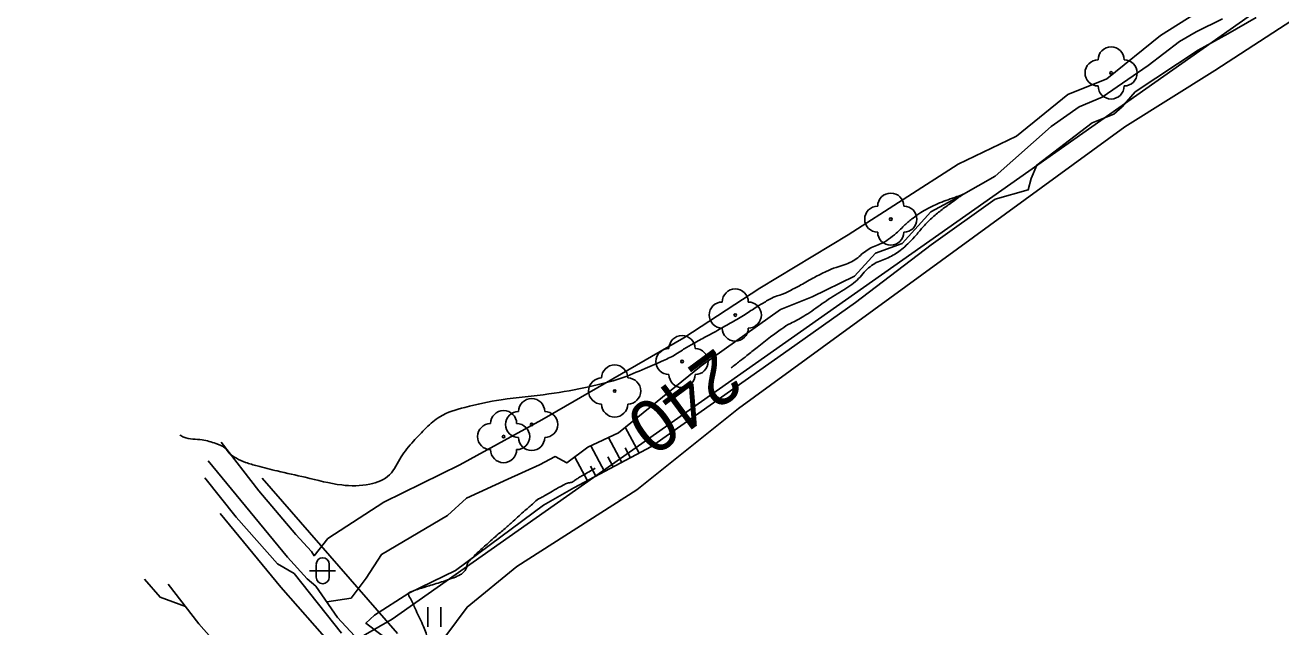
# Model space of a CAD drawing. Extents: x -478000 to -474772, y -1116847 to -1114124.
# Drawn here: x -477061.8 to -476965.5, y -1115018.8 to -1114972.6 of the extents above; entities that cross this region are included whole.
import ezdxf

# ---------------------------------------------------------------- set-up
doc = ezdxf.new("R2010")
doc.units = 0
for name, color, linetype in [('NadzemniVedeniSdelovaci', 7, 'Continuous'), ('ObPÚ', 7, 'Continuous'), ('OstatniRozhrani', 7, 'Continuous'), ('PopisneZnackyKultura', 7, 'Continuous'), ('RozhraniKultur', 7, 'Continuous'), ('RozhraniVozovky', 7, 'Continuous'), ('Teren_HranaSvahu', 7, 'Continuous'), ('Teren_PataSvahu', 7, 'Continuous'), ('Vrstevnice_hlavni', 7, 'Continuous'), ('Vrstevnice_popis', 7, 'Continuous'), ('VyskoveSrafy', 7, 'Continuous'), ('ZnackyStromu', 7, 'Continuous')]:
    doc.layers.add(name, color=color, linetype=linetype)

msp = doc.modelspace()

# ---------------------------------------------------------------- linework, layer by layer
at = {"layer": 'NadzemniVedeniSdelovaci'}
msp.add_line((-477043.667, -1115007.336), (-477033.291, -1115019.258), dxfattribs=at)
at = {"layer": 'ObPÚ'}
msp.add_lwpolyline([(-477231.42, -1115250.62), (-477154.22, -1115173.58), (-477134.18, -1115148.75), (-477133.16, -1115130.26), (-477132.09, -1115111.94), (-477138.91, -1115081.32), (-477119.74, -1115082.72), (-477097.23, -1115062.71), (-477080.55, -1115086.81), (-477072.47, -1115083.76), (-477045.85, -1115063.61), (-477043.93, -1115064.09), (-477025.31, -1115049.55), (-477043.48, -1115030.71), (-477047.46, -1115026.08), (-477033.7, -1115018.17), (-476933.96, -1114947.92), (-476834.35, -1114877.76), (-476714.64, -1114803.8), (-476602.93, -1114745.91), (-476491.34, -1114705.52), (-476390.17, -1114678.77), (-476300.68, -1114655.71)], dxfattribs=at)
at = {"layer": 'OstatniRozhrani'}
msp.add_lwpolyline([(-477052.686, -1115015.087), (-477051.49, -1115016.468), (-477049.548, -1115017.189)], dxfattribs=at)
at = {"layer": 'PopisneZnackyKultura'}
for p, q in [((-477039.525, -1115013.954), (-477039.525, -1115014.954)), ((-477038.525, -1115013.954), (-477038.525, -1115014.954)), ((-477040.025, -1115014.454), (-477038.025, -1115014.454)), ((-477030.962, -1115018.748), (-477030.962, -1115017.248)), ((-477029.962, -1115018.748), (-477029.962, -1115017.248))]:
    msp.add_line(p, q, dxfattribs=at)
for centre, start, end in [((-477039.017, -1115013.947), 0, 180), ((-477039.017, -1115014.947), 180, 0)]:
    msp.add_arc(centre, 0.5, start, end, dxfattribs=at)
at = {"layer": 'RozhraniKultur'}
for points in [[(-476813.378, -1114867.607), (-476821.938, -1114874.168), (-476829.956, -1114879.12), (-476839.311, -1114884.67), (-476847.948, -1114890.456), (-476853.558, -1114895.098), (-476860.628, -1114902.12), (-476864.524, -1114905.371), (-476870.261, -1114908.32), (-476877.101, -1114911.945), (-476885.307, -1114917.277), (-476891.328, -1114922.421), (-476896.91, -1114927.094), (-476901.992, -1114930.406), (-476908.574, -1114933.159), (-476916.772, -1114938.373), (-476929.13, -1114946.86), (-476942.484, -1114956.21), (-476956.292, -1114966.757), (-476970.592, -1114976.052), (-476977.493, -1114980.375)], [(-476977.493, -1114980.375), (-477007.129, -1115002.001), (-477014.915, -1115008.242), (-477024.119, -1115014.107), (-477027.941, -1115017.232), (-477029.578, -1115019.427), (-477026.9, -1115024.33), (-477020.646, -1115031.926), (-477009.657, -1115041.804), (-476989.625, -1115058.533), (-476972.959, -1115072.298), (-476959.884, -1115083.606), (-476949.57, -1115092.134), (-476936.86, -1115101.458), (-476916.801, -1115117.809), (-476898.41, -1115131.913), (-476893.29, -1115135.894), (-476884.407, -1115144.075), (-476873.818, -1115152.879), (-476869.38, -1115155.33)]]:
    msp.add_lwpolyline(points, dxfattribs=at)
at = {"layer": 'RozhraniVozovky'}
msp.add_line((-477050.872, -1115015.476), (-477048.51, -1115018.53), dxfattribs=at)
for points in [[(-476865.295, -1115165.15), (-476877.91, -1115155.046), (-476889.001, -1115146.126), (-476898.45, -1115138.608), (-476912.991, -1115126.893), (-476925.609, -1115116.576), (-476934.243, -1115109.589), (-476945.7, -1115100.408), (-476959.339, -1115089.601), (-476971.594, -1115079.598), (-476985.634, -1115068.114), (-477000.032, -1115056.392), (-477012.922, -1115045.335), (-477014.574, -1115043.636), (-477017.158, -1115041.291), (-477019.005, -1115039.725), (-477027.483, -1115031.623), (-477037.022, -1115021.628), (-477042.231, -1115015.698), (-477046.885, -1115010.045)], [(-477039.9, -1115028.25), (-477040.95, -1115027.09), (-477048.51, -1115018.53)]]:
    msp.add_lwpolyline(points, dxfattribs=at)
at = {"layer": 'Teren_HranaSvahu'}
for points in [[(-477046.814, -1115004.569), (-477043.911, -1115008.321), (-477041.082, -1115011.657), (-477039.877, -1115012.958), (-477039.679, -1115013.294), (-477038.62, -1115011.959), (-477034.327, -1115009.177), (-477028.512, -1115006.311), (-477022.216, -1115002.869), (-477011.316, -1114996.56), (-477005.49, -1114992.751), (-476998.708, -1114988.675), (-476990.274, -1114983.233), (-476985.811, -1114981.102), (-476981.858, -1114977.885), (-476978.88, -1114976.69), (-476974.77, -1114973.364), (-476968.548, -1114969.434)], [(-476967.424, -1114971.995), (-476969.6, -1114973.246), (-476971.86, -1114974.504), (-476976.701, -1114977.7), (-476977.711, -1114978.842), (-476978.346, -1114979.394), (-476979.993, -1114980.08), (-476984.258, -1114983.31), (-476984.676, -1114984.35), (-476984.921, -1114985.216), (-476987.44, -1114985.918), (-476992.351, -1114989.432), (-476998.162, -1114993.869), (-477003.252, -1114997.472), (-477013.794, -1115004.916), (-477019.756, -1115008.089), (-477022.074, -1115009.414), (-477025.351, -1115011.83), (-477028.825, -1115014.429), (-477032.418, -1115016.155), (-477035.055, -1115017.858), (-477035.707, -1115018.475), (-477032.661, -1115020.769)], [(-477037.585, -1115019.228), (-477041.218, -1115014.655), (-477042.497, -1115013.904), (-477045.656, -1115010.33), (-477048.061, -1115007.323)]]:
    msp.add_lwpolyline(points, dxfattribs=at)
at = {"layer": 'Teren_PataSvahu'}
for points in [[(-476969.998, -1114972.089), (-476972.036, -1114973.082), (-476973.311, -1114973.829), (-476975.701, -1114975.674), (-476979.23, -1114978.108), (-476981, -1114978.845), (-476983.152, -1114980.36), (-476987.439, -1114984.163), (-476990.054, -1114985.64), (-476992.38, -1114986.911), (-476994.571, -1114989.337), (-476996.61, -1114990.084), (-476998.235, -1114991.827), (-477001.467, -1114993.417), (-477003.916, -1114994.393), (-477009.987, -1114998.722), (-477016.342, -1115003.86), (-477018.68, -1115004.963), (-477020.285, -1115006.165), (-477021.194, -1115005.678), (-477022.397, -1115006.322), (-477024.812, -1115007.414), (-477027.993, -1115008.882), (-477029.446, -1115010.207), (-477034.517, -1115013.197), (-477035.689, -1115015.026), (-477036.844, -1115016.545), (-477038.709, -1115016.831)], [(-477047.805, -1115006.016), (-477041.728, -1115013.393), (-477040.206, -1115015.068), (-477039.547, -1115015.621), (-477037.87, -1115018.041), (-477036.57, -1115019.43), (-477033.66, -1115022.664), (-477026.482, -1115030.497), (-477018.989, -1115037.803), (-477016.248, -1115040.091)]]:
    msp.add_lwpolyline(points, dxfattribs=at)
at = {"layer": 'Vrstevnice_hlavni'}
for points in [[(-477049.979, -1115004.029), (-477049.673, -1115004.193), (-477048.26, -1115004.404), (-477047.204, -1115004.683), (-477046.505, -1115005.027), (-477046.164, -1115005.438), (-477045.639, -1115005.805), (-477044.929, -1115006.127), (-477044.034, -1115006.405), (-477042.508, -1115006.787), (-477040.351, -1115007.273), (-477037.562, -1115007.863), (-477035.407, -1115007.799), (-477033.886, -1115007.079), (-477033, -1115005.704), (-477032.062, -1115004.503), (-477031.073, -1115003.477), (-477030.034, -1115002.625), (-477028.119, -1115001.907), (-477025.328, -1115001.324), (-477021.663, -1115000.876), (-477018.599, -1115000.325), (-477016.138, -1114999.672), (-477014.278, -1114998.917), (-477012.873, -1114998.304), (-477011.923, -1114997.835), (-477011.428, -1114997.509), (-477010.705, -1114997.08), (-477009.754, -1114996.549), (-477008.574, -1114995.914), (-477007.491, -1114995.299), (-477006.505, -1114994.702), (-477005.616, -1114994.125), (-477004.874, -1114993.69), (-477004.28, -1114993.398), (-477003.833, -1114993.249), (-477003.188, -1114992.955), (-477002.345, -1114992.516), (-477001.305, -1114991.933), (-477000.403, -1114991.481), (-476999.64, -1114991.162), (-476999.016, -1114990.973), (-476998.464, -1114990.728), (-476997.985, -1114990.425), (-476997.579, -1114990.066), (-476997.143, -1114989.765), (-476996.676, -1114989.524), (-476996.178, -1114989.342), (-476995.627, -1114989.011), (-476995.023, -1114988.533), (-476994.365, -1114987.907), (-476993.741, -1114987.384), (-476993.153, -1114986.963), (-476992.599, -1114986.645), (-476992.009, -1114986.355), (-476991.383, -1114986.092), (-476990.719, -1114985.856), (-476990.255, -1114985.689), (-476989.991, -1114985.591), (-476989.925, -1114985.561), (-476989.901, -1114985.553), (-476989.919, -1114985.568), (-476989.977, -1114985.605), (-476990.02, -1114985.633), (-476990.048, -1114985.653), (-476990.061, -1114985.663), (-476990.326, -1114985.857), (-476990.841, -1114986.233), (-476991.608, -1114986.792), (-476992.308, -1114987.388), (-476992.94, -1114988.02), (-476993.504, -1114988.689), (-476994.025, -1114989.245), (-476994.503, -1114989.688), (-476994.937, -1114990.017), (-476995.402, -1114990.301), (-476995.899, -1114990.54), (-476996.428, -1114990.734), (-476996.92, -1114991.026), (-476997.375, -1114991.417), (-476997.795, -1114991.906), (-476998.298, -1114992.365), (-476998.884, -1114992.793), (-476999.553, -1114993.19), (-477000.214, -1114993.61), (-477000.867, -1114994.052), (-477001.512, -1114994.518), (-477002.106, -1114994.907), (-477002.649, -1114995.22), (-477003.142, -1114995.458), (-477003.814, -1114995.885), (-477004.665, -1114996.502)], [(-477004.665, -1114996.502), (-477005.695, -1114997.309), (-477006.489, -1114997.933), (-477007.047, -1114998.372), (-477007.691, -1114998.882)], [(-477017.894, -1115036.673), (-477018.831, -1115035.848), (-477019.673, -1115035.079), (-477020.422, -1115034.367), (-477021.076, -1115033.712), (-477022.168, -1115032.564), (-477023.697, -1115030.923), (-477025.662, -1115028.788), (-477027.122, -1115027.188), (-477028.074, -1115026.123), (-477028.52, -1115025.593), (-477029.034, -1115024.943), (-477029.617, -1115024.173), (-477030.269, -1115023.282), (-477030.708, -1115022.682), (-477030.934, -1115022.374), (-477030.946, -1115022.357), (-477030.928, -1115022.077), (-477030.878, -1115021.535), (-477030.797, -1115020.729), (-477030.934, -1115019.788), (-477031.286, -1115018.713), (-477031.856, -1115017.503), (-477032.238, -1115016.683), (-477032.433, -1115016.253), (-477032.44, -1115016.214), (-477032.443, -1115016.185), (-477032.441, -1115016.166), (-477032.435, -1115016.159), (-477032.431, -1115016.153), (-477032.428, -1115016.149), (-477032.426, -1115016.147), (-477032.373, -1115016.122), (-477032.267, -1115016.074), (-477032.11, -1115016.003), (-477031.64, -1115015.843), (-477030.858, -1115015.596), (-477029.763, -1115015.26), (-477028.959, -1115014.975), (-477028.444, -1115014.74), (-477028.219, -1115014.556), (-477028.06, -1115014.364), (-477027.968, -1115014.165), (-477027.943, -1115013.958), (-477027.674, -1115013.593), (-477027.161, -1115013.071), (-477026.405, -1115012.392), (-477025.889, -1115011.927), (-477025.616, -1115011.677), (-477025.583, -1115011.642), (-477025.534, -1115011.602), (-477025.469, -1115011.556), (-477025.387, -1115011.505), (-477025.033, -1115011.201), (-477024.407, -1115010.643), (-477023.509, -1115009.833), (-477022.858, -1115009.263), (-477022.455, -1115008.935), (-477022.299, -1115008.848), (-477021.991, -1115008.674), (-477021.533, -1115008.413), (-477020.923, -1115008.064), (-477020.468, -1115007.826), (-477020.167, -1115007.697), (-477020.021, -1115007.678), (-477019.883, -1115007.635), (-477019.754, -1115007.567), (-477019.633, -1115007.475), (-477019.398, -1115007.325), (-477019.047, -1115007.117), (-477018.115, -1115006.584)]]:
    msp.add_spline(points, degree=3, dxfattribs=at)
at = {"layer": 'VyskoveSrafy'}
for p, q in [((-477014.746, -1115005.423), (-477015.808, -1115003.428)), ((-477016.07, -1115006.128), (-477017.09, -1115004.213)), ((-477017.395, -1115006.832), (-477018.448, -1115004.853)), ((-477015.408, -1115005.775), (-477015.809, -1115005.022)), ((-477018.719, -1115007.537), (-477019.687, -1115005.717)), ((-477018.057, -1115007.185), (-477018.466, -1115006.416)), ((-477016.732, -1115006.48), (-477017.147, -1115005.701))]:
    msp.add_line(p, q, dxfattribs=at)
at = {"layer": 'ZnackyStromu'}
for centre in [(-476978.548, -1114976.243), (-476995.45, -1114987.463), (-477007.376, -1114994.821), (-477011.458, -1114998.391), (-477016.624, -1115000.652), (-477022.992, -1115003.223), (-477025.144, -1115004.15)]:
    msp.add_circle(centre, 0.1, dxfattribs=at)
for centre, start, end in [((-476978.548, -1114975.243), 0, 180), ((-476979.548, -1114976.243), 90, 270), ((-476977.548, -1114976.243), 270, 90), ((-476978.548, -1114977.243), 180, 0), ((-476995.45, -1114986.463), 0, 180), ((-476996.45, -1114987.463), 90, 270), ((-476994.45, -1114987.463), 270, 90), ((-476995.45, -1114988.463), 180, 0), ((-477007.376, -1114993.821), 0, 180), ((-477008.376, -1114994.821), 90, 270), ((-477006.376, -1114994.821), 270, 90), ((-477007.376, -1114995.821), 180, 0), ((-477011.458, -1114997.391), 0, 180), ((-477012.458, -1114998.391), 90, 270), ((-477010.458, -1114998.391), 270, 90), ((-477016.624, -1114999.652), 0, 180), ((-477017.624, -1115000.652), 90, 270), ((-477015.624, -1115000.652), 270, 90), ((-477011.458, -1114999.391), 180, 0), ((-477022.992, -1115002.223), 0, 180), ((-477016.624, -1115001.652), 180, 0), ((-477025.144, -1115003.15), 0, 180), ((-477023.992, -1115003.223), 90, 270), ((-477021.992, -1115003.223), 270, 90), ((-477026.144, -1115004.15), 90, 270), ((-477024.144, -1115004.15), 270, 90), ((-477022.992, -1115004.223), 180, 0), ((-477025.144, -1115005.15), 180, 0)]:
    msp.add_arc(centre, 1, start, end, dxfattribs=at)

# ---------------------------------------------------------------- texts
at = {"layer": 'Vrstevnice_popis'}
msp.add_text(' 240 ', height=4, rotation=216.46088, dxfattribs=at).set_placement((-477007.655, -1114996.369))

doc.saveas('drawing.dxf')
